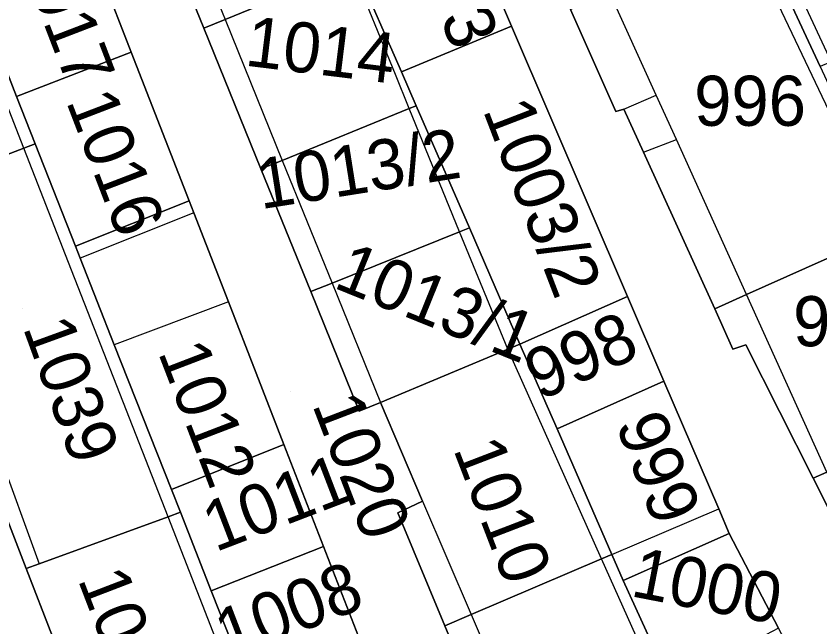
# Model space of a CAD drawing. Extents: x -263943 to -261149, y -1236934 to -1230686.
# Drawn here: x -262751.46 to -262719.38, y -1235391.16 to -1235366.77 of the extents above; entities that cross this region are included whole.
import ezdxf

# ---------------------------------------------------------------- set-up
doc = ezdxf.new("R2010")
doc.units = 0
for name, color, linetype in [('body_kn', 7, 'Continuous'), ('kladpar_druhypozemkov', 7, 'Continuous'), ('kladpar_hranice', 7, 'Continuous'), ('kladpar_parcelnecisla', 7, 'Continuous'), ('kladpar_plochy', 7, 'Continuous'), ('zappar_hrandruhpozemk', 7, 'Continuous')]:
    doc.layers.add(name, color=color, linetype=linetype)

msp = doc.modelspace()

# ---------------------------------------------------------------- linework, layer by layer
at = {"layer": 'body_kn'}
for p, q in [((-262743.12, -1235366.9), (-262743.12, -1235366.9)), ((-262743.12, -1235366.9), (-262743.12, -1235366.9)), ((-262743.97, -1235367.25), (-262743.97, -1235367.25)), ((-262731.69, -1235367.17), (-262731.69, -1235367.17)), ((-262746.86, -1235368.21), (-262746.86, -1235368.21)), ((-262736.08, -1235369), (-262736.08, -1235369)), ((-262736.32, -1235369.1), (-262736.32, -1235369.1)), ((-262751.44, -1235369.98), (-262751.44, -1235369.98)), ((-262751.44, -1235369.98), (-262751.44, -1235369.98)), ((-262725.91, -1235369.93), (-262725.91, -1235369.93)), ((-262735.77, -1235370.46), (-262735.77, -1235370.46)), ((-262735.77, -1235370.46), (-262735.77, -1235370.46)), ((-262735.49, -1235370.35), (-262735.49, -1235370.35)), ((-262735.49, -1235370.35), (-262735.49, -1235370.35)), ((-262727.53, -1235370.58), (-262727.53, -1235370.58)), ((-262727.2, -1235370.49), (-262727.2, -1235370.49)), ((-262727.2, -1235370.49), (-262727.2, -1235370.49)), ((-262750.7, -1235371.87), (-262750.7, -1235371.87)), ((-262750.7, -1235371.87), (-262750.7, -1235371.87)), ((-262725.11, -1235371.7), (-262725.11, -1235371.7)), ((-262751.15, -1235372.04), (-262751.15, -1235372.04)), ((-262751.15, -1235372.04), (-262751.15, -1235372.04)), ((-262726.42, -1235372.2), (-262726.42, -1235372.2)), ((-262726.42, -1235372.2), (-262726.42, -1235372.2)), ((-262740.84, -1235372.53), (-262740.84, -1235372.53)), ((-262740.84, -1235372.53), (-262740.84, -1235372.53)), ((-262741.69, -1235372.87), (-262741.69, -1235372.87)), ((-262744.55, -1235374.14), (-262744.55, -1235374.14)), ((-262744.36, -1235374.62), (-262744.36, -1235374.62)), ((-262744.36, -1235374.62), (-262744.36, -1235374.62)), ((-262733.76, -1235375.38), (-262733.76, -1235375.38)), ((-262733.76, -1235375.38), (-262733.76, -1235375.38)), ((-262733.37, -1235375.22), (-262733.37, -1235375.22)), ((-262733.37, -1235375.22), (-262733.37, -1235375.22)), ((-262749.09, -1235375.95), (-262749.09, -1235375.95)), ((-262748.9, -1235376.43), (-262748.9, -1235376.43)), ((-262748.9, -1235376.43), (-262748.9, -1235376.43)), ((-262749.36, -1235376.61), (-262749.36, -1235376.61)), ((-262738.85, -1235377.43), (-262738.85, -1235377.43)), ((-262738.85, -1235377.43), (-262738.85, -1235377.43)), ((-262739.7, -1235377.77), (-262739.7, -1235377.77)), ((-262727.06, -1235377.96), (-262727.06, -1235377.96)), ((-262722.31, -1235377.88), (-262722.31, -1235377.88)), ((-262722.31, -1235377.88), (-262722.31, -1235377.88)), ((-262742.98, -1235378.17), (-262742.98, -1235378.17)), ((-262742.98, -1235378.17), (-262742.98, -1235378.17)), ((-262723.58, -1235378.45), (-262723.58, -1235378.45)), ((-262747.54, -1235379.89), (-262747.54, -1235379.89)), ((-262747.54, -1235379.89), (-262747.54, -1235379.89)), ((-262731.35, -1235379.86), (-262731.35, -1235379.86)), ((-262731.35, -1235379.86), (-262731.35, -1235379.86)), ((-262722.34, -1235379.89), (-262722.34, -1235379.89)), ((-262731.84, -1235380.07), (-262731.84, -1235380.07)), ((-262731.84, -1235380.07), (-262731.84, -1235380.07)), ((-262722.85, -1235380.06), (-262722.85, -1235380.06)), ((-262725.61, -1235381.34), (-262725.61, -1235381.34)), ((-262736.92, -1235382.2), (-262736.92, -1235382.2)), ((-262737.77, -1235382.54), (-262737.77, -1235382.54)), ((-262729.87, -1235383.25), (-262729.87, -1235383.25)), ((-262740.77, -1235383.87), (-262740.77, -1235383.87)), ((-262719.65, -1235385.22), (-262719.65, -1235385.22)), ((-262719.65, -1235385.22), (-262719.65, -1235385.22)), ((-262745.26, -1235385.67), (-262745.26, -1235385.67)), ((-262735.24, -1235386.14), (-262735.24, -1235386.14)), ((-262735.24, -1235386.14), (-262735.24, -1235386.14)), ((-262744.9, -1235386.58), (-262744.9, -1235386.58)), ((-262744.9, -1235386.58), (-262744.9, -1235386.58)), ((-262736.23, -1235386.6), (-262736.23, -1235386.6)), ((-262723.42, -1235386.44), (-262723.42, -1235386.44)), ((-262745.39, -1235386.76), (-262745.39, -1235386.76)), ((-262745.39, -1235386.76), (-262745.39, -1235386.76)), ((-262723, -1235387.43), (-262723, -1235387.43)), ((-262739.19, -1235387.95), (-262739.19, -1235387.95)), ((-262727.68, -1235388.26), (-262727.68, -1235388.26)), ((-262727.68, -1235388.26), (-262727.68, -1235388.26)), ((-262728.09, -1235388.43), (-262728.09, -1235388.43)), ((-262728.09, -1235388.43), (-262728.09, -1235388.43)), ((-262751.05, -1235388.82), (-262751.05, -1235388.82)), ((-262750.54, -1235388.63), (-262750.54, -1235388.63)), ((-262727.23, -1235389.3), (-262727.23, -1235389.3)), ((-262727.23, -1235389.3), (-262727.23, -1235389.3)), ((-262743.67, -1235389.71), (-262743.67, -1235389.71)), ((-262733.3, -1235390.66), (-262733.3, -1235390.66)), ((-262733.3, -1235390.66), (-262733.3, -1235390.66)), ((-262734.35, -1235391.11), (-262734.35, -1235391.11))]:
    msp.add_line(p, q, dxfattribs=at)
at = {"layer": 'kladpar_druhypozemkov'}
for p, q in [((-262739.54, -1235367.47), (-262739.54, -1235367.47)), ((-262722.5, -1235369.35), (-262722.5, -1235369.35)), ((-262732.8, -1235370.85), (-262732.8, -1235370.85)), ((-262746.89, -1235371.8), (-262746.89, -1235371.8)), ((-262737.9, -1235372.15), (-262737.9, -1235372.15)), ((-262734.68, -1235377.62), (-262734.68, -1235377.62)), ((-262751.2, -1235378.45), (-262751.2, -1235378.45)), ((-262728.7, -1235379.45), (-262728.7, -1235379.45)), ((-262743.36, -1235381.5), (-262743.36, -1235381.5)), ((-262740.5, -1235381.75), (-262740.5, -1235381.75)), ((-262725.44, -1235384.09), (-262725.44, -1235384.09)), ((-262731.76, -1235385.54), (-262731.76, -1235385.54)), ((-262742.17, -1235386.06), (-262742.17, -1235386.06)), ((-262723.9, -1235388.85), (-262723.9, -1235388.85)), ((-262740.6, -1235389.45), (-262740.6, -1235389.45)), ((-262746.35, -1235391.04), (-262746.35, -1235391.04))]:
    msp.add_line(p, q, dxfattribs=at)
at = {"layer": 'kladpar_hranice'}
for points in [[(-262753.31, -1235338.85), (-262748.99, -1235338.67), (-262748.71, -1235347.06), (-262748.36, -1235352.57), (-262746.91, -1235356.97), (-262745.54, -1235360.95), (-262746.39, -1235361.29), (-262743.97, -1235367.25), (-262741.69, -1235372.87), (-262739.7, -1235377.77), (-262737.77, -1235382.54), (-262736.92, -1235382.2), (-262735.24, -1235386.14)], [(-262735.24, -1235386.14), (-262736.23, -1235386.6), (-262734.35, -1235391.11), (-262733.6, -1235392.91), (-262732.92, -1235394.55), (-262730.89, -1235399.43), (-262726.75, -1235409.37), (-262726.33, -1235409.2), (-262725.3, -1235410.9), (-262729.28, -1235413.44), (-262729.86, -1235411.96), (-262729.29, -1235411.75), (-262733.39, -1235401.17), (-262733.98, -1235401.37), (-262735.65, -1235397.07), (-262737.33, -1235392.74), (-262739.19, -1235387.95), (-262740.77, -1235383.87), (-262742.98, -1235378.17), (-262744.36, -1235374.62), (-262744.55, -1235374.14), (-262746.86, -1235368.21), (-262749.18, -1235362.23), (-262751.68, -1235348.93)], [(-262713.13, -1235366.11), (-262718.93, -1235368.59), (-262719.37, -1235368.78), (-262722.04, -1235363.03), (-262722.76, -1235361.49), (-262722.32, -1235361.3), (-262716.44, -1235358.71), (-262715.81, -1235358.44), (-262712.62, -1235365.89), (-262713.13, -1235366.11)], [(-262738.06, -1235364.83), (-262743.12, -1235366.9), (-262743.97, -1235367.25), (-262746.39, -1235361.29), (-262745.54, -1235360.95), (-262740.54, -1235358.74), (-262738.81, -1235362.72), (-262737.92, -1235364.77), (-262738.06, -1235364.83)], [(-262737.92, -1235364.77), (-262738.81, -1235362.72), (-262734.42, -1235360.79), (-262731.69, -1235367.17), (-262736.08, -1235369), (-262737.92, -1235364.77)], [(-262719.65, -1235385.22), (-262717.44, -1235389.6), (-262717.82, -1235389.79), (-262717.24, -1235390.95), (-262712.61, -1235400.29), (-262711.68, -1235399.78), (-262714.8, -1235403.07), (-262719.39, -1235394.32), (-262721.03, -1235391.2), (-262723, -1235387.43), (-262723.42, -1235386.44), (-262725.61, -1235381.34), (-262727.06, -1235377.96), (-262731.69, -1235367.17), (-262734.42, -1235360.79)], [(-262752.39, -1235367.57), (-262753.73, -1235364.06), (-262749.18, -1235362.23), (-262746.86, -1235368.21), (-262751.44, -1235369.98), (-262752.39, -1235367.57)], [(-262716.38, -1235375.24), (-262716.73, -1235375.4), (-262722.31, -1235377.88), (-262723.58, -1235378.45), (-262726.42, -1235372.2), (-262727.2, -1235370.49), (-262727.53, -1235370.58), (-262729.33, -1235366.51), (-262727.8, -1235365.75), (-262722.49, -1235363.24), (-262722.04, -1235363.03), (-262719.37, -1235368.78), (-262716.38, -1235375.24)], [(-262735.49, -1235370.35), (-262735.77, -1235370.46), (-262740.84, -1235372.53), (-262741.69, -1235372.87), (-262743.97, -1235367.25), (-262743.12, -1235366.9), (-262738.06, -1235364.83), (-262737.92, -1235364.77), (-262736.08, -1235369), (-262735.49, -1235370.35)], [(-262729.33, -1235366.51), (-262727.53, -1235370.58), (-262727.2, -1235370.49), (-262726.42, -1235372.2), (-262723.58, -1235378.45), (-262722.85, -1235380.06), (-262722.34, -1235379.89), (-262719.65, -1235385.22)], [(-262733.37, -1235375.22), (-262735.49, -1235370.35), (-262736.08, -1235369), (-262731.69, -1235367.17), (-262727.06, -1235377.96), (-262731.35, -1235379.86), (-262733.37, -1235375.22)], [(-262750.7, -1235371.87), (-262751.15, -1235372.04), (-262755.92, -1235373.88), (-262756.7, -1235374.18), (-262758.21, -1235369.9), (-262752.83, -1235367.75), (-262752.39, -1235367.57), (-262751.44, -1235369.98), (-262750.7, -1235371.87)], [(-262751.44, -1235369.98), (-262746.86, -1235368.21), (-262744.55, -1235374.14), (-262749.09, -1235375.95), (-262750.7, -1235371.87), (-262751.44, -1235369.98)], [(-262733.76, -1235375.38), (-262738.85, -1235377.43), (-262739.7, -1235377.77), (-262741.69, -1235372.87), (-262740.84, -1235372.53), (-262735.77, -1235370.46), (-262735.49, -1235370.35), (-262733.37, -1235375.22), (-262733.76, -1235375.38)], [(-262748.9, -1235376.43), (-262747.54, -1235379.89), (-262745.26, -1235385.67), (-262744.9, -1235386.58), (-262745.39, -1235386.76), (-262750.54, -1235388.63), (-262751.05, -1235388.82), (-262756.7, -1235374.18), (-262755.92, -1235373.88), (-262751.15, -1235372.04), (-262750.7, -1235371.87), (-262749.09, -1235375.95), (-262748.9, -1235376.43)], [(-262756.7, -1235374.18), (-262751.05, -1235388.82), (-262747.9, -1235396.97), (-262744.98, -1235404.54), (-262743.1, -1235409.39)], [(-262747.54, -1235379.89), (-262748.9, -1235376.43), (-262749.09, -1235375.95), (-262744.55, -1235374.14), (-262744.36, -1235374.62), (-262742.98, -1235378.17), (-262740.77, -1235383.87), (-262745.26, -1235385.67), (-262747.54, -1235379.89)], [(-262731.84, -1235380.07), (-262736.92, -1235382.2), (-262737.77, -1235382.54), (-262739.7, -1235377.77), (-262738.85, -1235377.43), (-262733.76, -1235375.38), (-262733.37, -1235375.22), (-262731.35, -1235379.86), (-262731.84, -1235380.07)], [(-262713.09, -1235382.33), (-262713.39, -1235382.46), (-262719.1, -1235384.97), (-262719.65, -1235385.22), (-262722.34, -1235379.89), (-262722.85, -1235380.06), (-262723.58, -1235378.45), (-262722.31, -1235377.88), (-262716.73, -1235375.4), (-262716.38, -1235375.24), (-262716.16, -1235375.72), (-262713.09, -1235382.33)], [(-262731.35, -1235379.86), (-262727.06, -1235377.96), (-262725.61, -1235381.34), (-262729.87, -1235383.25), (-262731.35, -1235379.86)], [(-262727.68, -1235388.26), (-262728.09, -1235388.43), (-262733.3, -1235390.66), (-262734.35, -1235391.11), (-262736.23, -1235386.6), (-262735.24, -1235386.14), (-262736.92, -1235382.2), (-262731.84, -1235380.07), (-262731.35, -1235379.86), (-262729.87, -1235383.25), (-262727.68, -1235388.26)], [(-262727.23, -1235389.3), (-262727.68, -1235388.26), (-262729.87, -1235383.25), (-262725.61, -1235381.34), (-262723.42, -1235386.44), (-262723, -1235387.43), (-262727.23, -1235389.3)], [(-262744.9, -1235386.58), (-262745.26, -1235385.67), (-262740.77, -1235383.87), (-262739.19, -1235387.95), (-262743.67, -1235389.71), (-262744.9, -1235386.58)], [(-262719.65, -1235385.22), (-262719.1, -1235384.97), (-262716.92, -1235389.34), (-262716.33, -1235390.51), (-262711.68, -1235399.78), (-262712.61, -1235400.29), (-262717.24, -1235390.95), (-262717.82, -1235389.79), (-262717.44, -1235389.6), (-262719.65, -1235385.22)], [(-262741.79, -1235394.48), (-262741.72, -1235394.65), (-262742.23, -1235394.84), (-262747.9, -1235396.97), (-262751.05, -1235388.82), (-262750.54, -1235388.63), (-262745.39, -1235386.76), (-262744.9, -1235386.58), (-262743.67, -1235389.71), (-262741.79, -1235394.48)], [(-262727.23, -1235389.3), (-262723, -1235387.43), (-262721.03, -1235391.2), (-262725.33, -1235393.47), (-262727.23, -1235389.3)], [(-262740.1, -1235398.78), (-262741.72, -1235394.65), (-262741.79, -1235394.48), (-262743.67, -1235389.71), (-262739.19, -1235387.95), (-262737.33, -1235392.74), (-262735.65, -1235397.07), (-262740.1, -1235398.78)], [(-262725.33, -1235393.47), (-262724.01, -1235396.35), (-262724.46, -1235396.55), (-262729.77, -1235398.92), (-262730.43, -1235399.22), (-262730.89, -1235399.43), (-262732.92, -1235394.55), (-262733.6, -1235392.91), (-262734.35, -1235391.11), (-262733.3, -1235390.66), (-262728.09, -1235388.43), (-262727.68, -1235388.26), (-262727.23, -1235389.3), (-262725.33, -1235393.47)]]:
    msp.add_lwpolyline(points, dxfattribs=at)
at = {"layer": 'kladpar_plochy'}
for points in [[(-262713.13, -1235366.11), (-262718.93, -1235368.59), (-262719.37, -1235368.78), (-262722.04, -1235363.03), (-262722.76, -1235361.49), (-262722.32, -1235361.3), (-262716.44, -1235358.71), (-262715.81, -1235358.44), (-262712.62, -1235365.89)], [(-262738.06, -1235364.83), (-262743.12, -1235366.9), (-262743.97, -1235367.25), (-262746.39, -1235361.29), (-262745.54, -1235360.95), (-262740.54, -1235358.74), (-262738.81, -1235362.72), (-262737.92, -1235364.77)], [(-262737.92, -1235364.77), (-262738.81, -1235362.72), (-262734.42, -1235360.79), (-262731.69, -1235367.17), (-262736.08, -1235369)], [(-262752.39, -1235367.57), (-262753.73, -1235364.06), (-262749.18, -1235362.23), (-262746.86, -1235368.21), (-262751.44, -1235369.98)], [(-262716.38, -1235375.24), (-262716.73, -1235375.4), (-262722.31, -1235377.88), (-262723.58, -1235378.45), (-262726.42, -1235372.2), (-262727.2, -1235370.49), (-262727.53, -1235370.58), (-262729.33, -1235366.51), (-262727.8, -1235365.75), (-262722.49, -1235363.24), (-262722.04, -1235363.03), (-262719.37, -1235368.78)], [(-262735.49, -1235370.35), (-262735.77, -1235370.46), (-262740.84, -1235372.53), (-262741.69, -1235372.87), (-262743.97, -1235367.25), (-262743.12, -1235366.9), (-262738.06, -1235364.83), (-262737.92, -1235364.77), (-262736.08, -1235369)], [(-262733.37, -1235375.22), (-262735.49, -1235370.35), (-262736.08, -1235369), (-262731.69, -1235367.17), (-262727.06, -1235377.96), (-262731.35, -1235379.86)], [(-262750.7, -1235371.87), (-262751.15, -1235372.04), (-262755.92, -1235373.88), (-262756.7, -1235374.18), (-262758.21, -1235369.9), (-262752.83, -1235367.75), (-262752.39, -1235367.57), (-262751.44, -1235369.98)], [(-262751.44, -1235369.98), (-262746.86, -1235368.21), (-262744.55, -1235374.14), (-262749.09, -1235375.95), (-262750.7, -1235371.87)], [(-262733.76, -1235375.38), (-262738.85, -1235377.43), (-262739.7, -1235377.77), (-262741.69, -1235372.87), (-262740.84, -1235372.53), (-262735.77, -1235370.46), (-262735.49, -1235370.35), (-262733.37, -1235375.22)], [(-262748.9, -1235376.43), (-262747.54, -1235379.89), (-262745.26, -1235385.67), (-262744.9, -1235386.58), (-262745.39, -1235386.76), (-262750.54, -1235388.63), (-262751.05, -1235388.82), (-262756.7, -1235374.18), (-262755.92, -1235373.88), (-262751.15, -1235372.04), (-262750.7, -1235371.87), (-262749.09, -1235375.95)], [(-262747.54, -1235379.89), (-262748.9, -1235376.43), (-262749.09, -1235375.95), (-262744.55, -1235374.14), (-262744.36, -1235374.62), (-262742.98, -1235378.17), (-262740.77, -1235383.87), (-262745.26, -1235385.67)], [(-262731.84, -1235380.07), (-262736.92, -1235382.2), (-262737.77, -1235382.54), (-262739.7, -1235377.77), (-262738.85, -1235377.43), (-262733.76, -1235375.38), (-262733.37, -1235375.22), (-262731.35, -1235379.86)], [(-262713.09, -1235382.33), (-262713.39, -1235382.46), (-262719.1, -1235384.97), (-262719.65, -1235385.22), (-262722.34, -1235379.89), (-262722.85, -1235380.06), (-262723.58, -1235378.45), (-262722.31, -1235377.88), (-262716.73, -1235375.4), (-262716.38, -1235375.24), (-262716.16, -1235375.72)], [(-262731.35, -1235379.86), (-262727.06, -1235377.96), (-262725.61, -1235381.34), (-262729.87, -1235383.25)], [(-262727.68, -1235388.26), (-262728.09, -1235388.43), (-262733.3, -1235390.66), (-262734.35, -1235391.11), (-262736.23, -1235386.6), (-262735.24, -1235386.14), (-262736.92, -1235382.2), (-262731.84, -1235380.07), (-262731.35, -1235379.86), (-262729.87, -1235383.25)], [(-262727.23, -1235389.3), (-262727.68, -1235388.26), (-262729.87, -1235383.25), (-262725.61, -1235381.34), (-262723.42, -1235386.44), (-262723, -1235387.43)], [(-262744.9, -1235386.58), (-262745.26, -1235385.67), (-262740.77, -1235383.87), (-262739.19, -1235387.95), (-262743.67, -1235389.71)], [(-262719.65, -1235385.22), (-262719.1, -1235384.97), (-262716.92, -1235389.34), (-262716.33, -1235390.51), (-262711.68, -1235399.78), (-262712.61, -1235400.29), (-262717.24, -1235390.95), (-262717.82, -1235389.79), (-262717.44, -1235389.6)], [(-262741.79, -1235394.48), (-262741.72, -1235394.65), (-262742.23, -1235394.84), (-262747.9, -1235396.97), (-262751.05, -1235388.82), (-262750.54, -1235388.63), (-262745.39, -1235386.76), (-262744.9, -1235386.58), (-262743.67, -1235389.71)], [(-262727.23, -1235389.3), (-262723, -1235387.43), (-262721.03, -1235391.2), (-262725.33, -1235393.47)], [(-262740.1, -1235398.78), (-262741.72, -1235394.65), (-262741.79, -1235394.48), (-262743.67, -1235389.71), (-262739.19, -1235387.95), (-262737.33, -1235392.74), (-262735.65, -1235397.07)], [(-262725.33, -1235393.47), (-262724.01, -1235396.35), (-262724.46, -1235396.55), (-262729.77, -1235398.92), (-262730.43, -1235399.22), (-262730.89, -1235399.43), (-262732.92, -1235394.55), (-262733.6, -1235392.91), (-262734.35, -1235391.11), (-262733.3, -1235390.66), (-262728.09, -1235388.43), (-262727.68, -1235388.26), (-262727.23, -1235389.3)]]:
    msp.add_lwpolyline(points, close=True, dxfattribs=at)
for points in [[(-262729.33, -1235366.51), (-262727.53, -1235370.58), (-262727.2, -1235370.49), (-262726.42, -1235372.2), (-262723.58, -1235378.45), (-262722.85, -1235380.06), (-262722.34, -1235379.89), (-262719.65, -1235385.22), (-262717.44, -1235389.6), (-262717.82, -1235389.79), (-262717.24, -1235390.95), (-262712.61, -1235400.29), (-262711.68, -1235399.78), (-262714.8, -1235403.07), (-262719.39, -1235394.32), (-262721.03, -1235391.2), (-262723, -1235387.43), (-262723.42, -1235386.44), (-262725.61, -1235381.34), (-262727.06, -1235377.96), (-262731.69, -1235367.17), (-262734.42, -1235360.79)], [(-262746.39, -1235361.29), (-262743.97, -1235367.25), (-262741.69, -1235372.87), (-262739.7, -1235377.77), (-262737.77, -1235382.54), (-262736.92, -1235382.2), (-262735.24, -1235386.14), (-262736.23, -1235386.6), (-262734.35, -1235391.11), (-262733.6, -1235392.91)], [(-262737.33, -1235392.74), (-262739.19, -1235387.95), (-262740.77, -1235383.87), (-262742.98, -1235378.17), (-262744.36, -1235374.62), (-262744.55, -1235374.14), (-262746.86, -1235368.21), (-262749.18, -1235362.23)], [(-262756.7, -1235374.18), (-262751.05, -1235388.82), (-262747.9, -1235396.97), (-262744.98, -1235404.54), (-262743.1, -1235409.39), (-262739.88, -1235417.72), (-262739.27, -1235419.31), (-262742.66, -1235420.75), (-262744.4, -1235416.65), (-262746.93, -1235410.68), (-262749.51, -1235411.73), (-262750.05, -1235411.95), (-262752.12, -1235407.05), (-262748.9, -1235405.69), (-262751.6, -1235398.38)]]:
    msp.add_lwpolyline(points, dxfattribs=at)
at = {"layer": 'zappar_hrandruhpozemk'}
for p, q in [((-262745.54, -1235360.95), (-262743.12, -1235366.9)), ((-262722.32, -1235361.3), (-262718.93, -1235368.59)), ((-262722.49, -1235363.24), (-262716.73, -1235375.4)), ((-262743.12, -1235366.9), (-262740.84, -1235372.53)), ((-262751.15, -1235372.04), (-262752.83, -1235367.75)), ((-262727.2, -1235370.49), (-262725.91, -1235369.93)), ((-262733.76, -1235375.38), (-262735.77, -1235370.46)), ((-262726.42, -1235372.2), (-262725.11, -1235371.7)), ((-262749.36, -1235376.61), (-262751.15, -1235372.04)), ((-262740.84, -1235372.53), (-262738.85, -1235377.43)), ((-262755.92, -1235373.88), (-262750.54, -1235388.63)), ((-262744.36, -1235374.62), (-262748.9, -1235376.43)), ((-262731.84, -1235380.07), (-262733.76, -1235375.38)), ((-262745.39, -1235386.76), (-262749.36, -1235376.61)), ((-262738.85, -1235377.43), (-262736.92, -1235382.2)), ((-262719.1, -1235384.97), (-262722.31, -1235377.88)), ((-262742.98, -1235378.17), (-262747.54, -1235379.89)), ((-262728.09, -1235388.43), (-262731.84, -1235380.07)), ((-262735.24, -1235386.14), (-262733.3, -1235390.66)), ((-262727.68, -1235388.26), (-262723.42, -1235386.44)), ((-262742.23, -1235394.84), (-262745.39, -1235386.76)), ((-262724.46, -1235396.55), (-262728.09, -1235388.43))]:
    msp.add_line(p, q, dxfattribs=at)
for points in [[(-262735.77, -1235370.46), (-262736.32, -1235369.1), (-262738.06, -1235364.83)], [(-262722.31, -1235377.88), (-262725.11, -1235371.7), (-262725.91, -1235369.93), (-262727.8, -1235365.75)], [(-262733.3, -1235390.66), (-262732.53, -1235392.45), (-262731.83, -1235394.09), (-262729.77, -1235398.92)]]:
    msp.add_lwpolyline(points, dxfattribs=at)

# ---------------------------------------------------------------- texts
at = {"layer": 'kladpar_parcelnecisla'}
for s, rotation, p in [('993', 291, (-262735.614, -1235364.056)), ('1017', 291, (-262751.459, -1235364.214)), ('1014', 353, (-262742.367, -1235368.74)), ('1016', 291, (-262749.476, -1235370.17)), ('1003/2', 291, (-262732.845, -1235370.518)), ('1013/2', 9, (-262741.693, -1235374.483)), ('1013/1', 338, (-262738.847, -1235377.59)), ('998', 24, (-262730.565, -1235382.138)), ('1039', 290, (-262751.199, -1235379.199)), ('1012', 291, (-262745.807, -1235380.189)), ('1020', 291, (-262739.655, -1235382.278)), ('999', 291, (-262727.547, -1235383.052)), ('1010', 291, (-262734.027, -1235384.051)), ('1011', 21, (-262743.508, -1235388.179)), ('1000', 349, (-262726.984, -1235389.918)), ('1008', 21, (-262743.014, -1235392.482)), ('1043', 291, (-262749.009, -1235389.252))]:
    msp.add_text(s, height=2, rotation=rotation, dxfattribs=at).set_placement(p)
for s, p in [('996', (-262724.399, -1235371.15)), ('997', (-262720.452, -1235379.95))]:
    msp.add_text(s, height=2, dxfattribs=at).set_placement(p)

doc.saveas('drawing.dxf')
